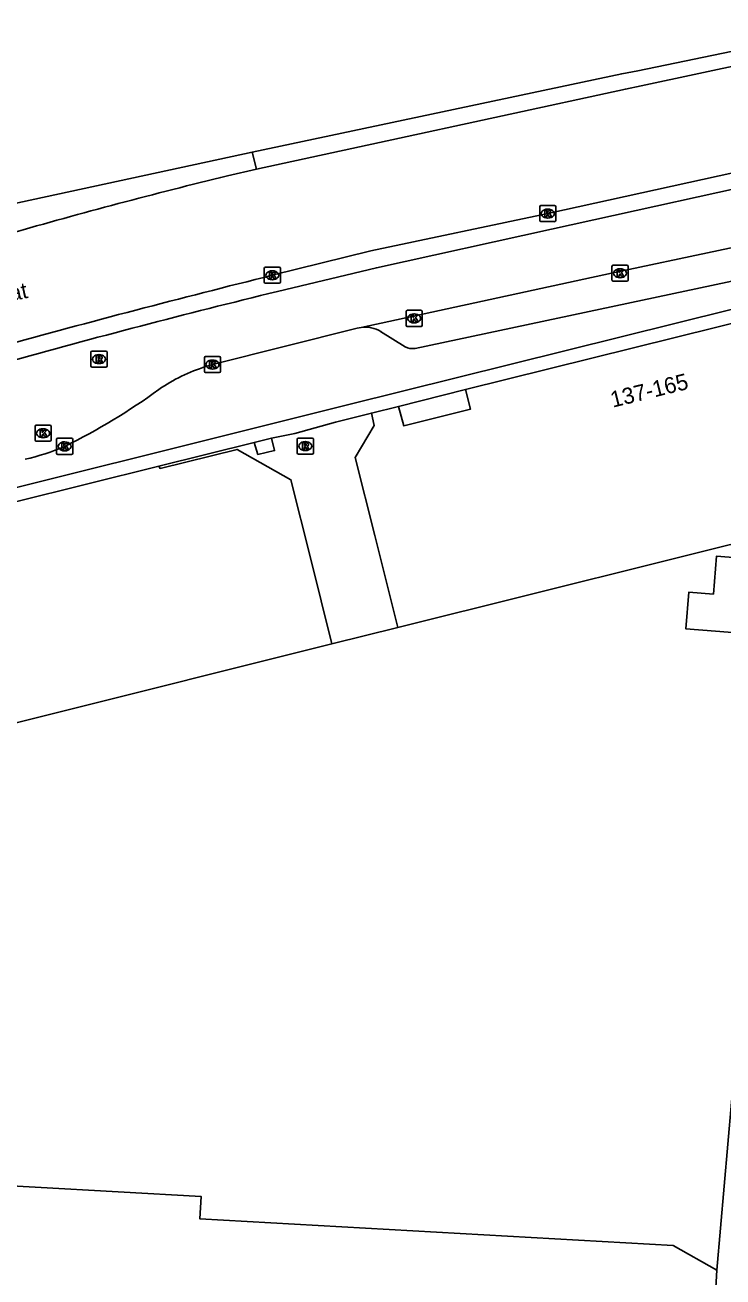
# Model space of a CAD drawing. Extents: x 160861 to 161308, y 384024 to 384878.
# Drawn here: x 160913.4 to 160956.7, y 384793.3 to 384871 of the extents above; entities that cross this region are included whole.
import ezdxf

# ---------------------------------------------------------------- set-up
doc = ezdxf.new("R2010")
doc.units = 0
for name, color, linetype in [('IMGEO_Berm_gesloten', 7, 'Continuous'), ('IMGEO_Erf', 7, 'Continuous'), ('IMGEO_Fietspad_gesloten', 7, 'Continuous'), ('IMGEO_Kolk', 7, 'Continuous'), ('IMGEO_Openbare_ruimte_label', 7, 'Continuous'), ('IMGEO_Pand', 7, 'Continuous'), ('IMGEO_Pand_nummerreeks', 7, 'Continuous'), ('IMGEO_Pand_overbouw', 7, 'Continuous'), ('IMGEO_Rijbaan_lokaal_open', 7, 'Continuous'), ('IMGEO_Rijbaan_regionaal_gesloten', 7, 'Continuous'), ('IMGEO_Rioolput', 7, 'Continuous'), ('IMGEO_Voetpad_open', 7, 'Continuous')]:
    doc.layers.add(name, color=color, linetype=linetype)

msp = doc.modelspace()

# ---------------------------------------------------------------- linework, layer by layer
at = {"layer": 'IMGEO_Berm_gesloten'}
msp.add_lwpolyline([(160927.748, 384862.071), (160927.48, 384863.128)], dxfattribs=at)
at = {"layer": 'IMGEO_Erf'}
msp.add_lwpolyline([(160958.824, 384833.185), (160959.001, 384835.447), (160966.05, 384834.898), (160966.234, 384837.263), (160956.254, 384838.041), (160956.072, 384835.701), (160954.55, 384835.82), (160954.371, 384833.532), (160958.824, 384833.185)], dxfattribs=at)
at = {"layer": 'IMGEO_Fietspad_gesloten'}
for points in [[(160965.533, 384862.563), (160961.596, 384861.765), (160946.03, 384858.331), (160935.179, 384855.945), (160929.044, 384854.477)], [(160934.227, 384852.244), (160949.744, 384855.609), (160963.013, 384858.428), (160966.201, 384859.13)], [(160924.6, 384849.813), (160925.012, 384849.941), (160933.981, 384852.191), (160934.227, 384852.244)]]:
    msp.add_lwpolyline(points, dxfattribs=at)
for centre, radius, start, end in [((161060.371, 384317.53), 552.774, 103.74361, 105.55791), ((160927.766, 384839.602), 10.69, 107.22679, 124.63629), ((160898.999, 384879.313), 38.349, 296.06689, 306.27811), ((160910.796, 384856.306), 12.508, 281.98394, 293.8334)]:
    msp.add_arc(centre, radius, start, end, dxfattribs=at)
at = {"layer": 'IMGEO_Kolk'}
for p, q in [((160945.3, 384858.88), (160945.3, 384859.732)), ((160945.375, 384859.806), (160946.227, 384859.806)), ((160946.301, 384859.732), (160946.301, 384858.88)), ((160945.811, 384859.026), (160945.786, 384859.026)), ((160945.788, 384859.586), (160945.813, 384859.586)), ((160946.227, 384858.806), (160945.375, 384858.806)), ((160928.223, 384855.054), (160928.223, 384855.906)), ((160928.298, 384855.98), (160929.15, 384855.98)), ((160929.224, 384855.906), (160929.224, 384855.054)), ((160949.782, 384855.179), (160949.782, 384856.031)), ((160949.857, 384856.105), (160950.709, 384856.105)), ((160950.27, 384855.885), (160950.295, 384855.885)), ((160950.783, 384856.031), (160950.783, 384855.179)), ((160928.734, 384855.2), (160928.709, 384855.2)), ((160928.711, 384855.76), (160928.736, 384855.76)), ((160950.709, 384855.105), (160949.857, 384855.105)), ((160950.293, 384855.325), (160950.268, 384855.325)), ((160929.15, 384854.98), (160928.298, 384854.98)), ((160937.017, 384852.379), (160937.017, 384853.231)), ((160937.092, 384853.305), (160937.944, 384853.305)), ((160937.505, 384853.085), (160937.53, 384853.085)), ((160938.018, 384853.231), (160938.018, 384852.379)), ((160937.944, 384852.305), (160937.092, 384852.305)), ((160937.528, 384852.525), (160937.503, 384852.525)), ((160924.511, 384849.515), (160924.511, 384850.367)), ((160924.586, 384850.441), (160925.438, 384850.441)), ((160925.512, 384850.367), (160925.512, 384849.515)), ((160925.022, 384849.661), (160924.997, 384849.661)), ((160924.999, 384850.221), (160925.024, 384850.221)), ((160925.438, 384849.441), (160924.586, 384849.441)), ((160914.012, 384845.253), (160914.012, 384846.105)), ((160914.087, 384846.179), (160914.939, 384846.179)), ((160914.5, 384845.959), (160914.525, 384845.959)), ((160915.013, 384846.105), (160915.013, 384845.253)), ((160914.939, 384845.179), (160914.087, 384845.179)), ((160914.523, 384845.399), (160914.498, 384845.399)), ((160915.349, 384844.439), (160915.349, 384845.291)), ((160915.424, 384845.365), (160916.276, 384845.365)), ((160915.837, 384845.145), (160915.862, 384845.145)), ((160916.35, 384845.291), (160916.35, 384844.439)), ((160916.276, 384844.365), (160915.424, 384844.365)), ((160915.86, 384844.585), (160915.835, 384844.585))]:
    msp.add_line(p, q, dxfattribs=at)
for points in [[(160945.3, 384858.88), (160945.3, 384859.732)], [(160945.375, 384859.806), (160946.227, 384859.806)], [(160946.301, 384859.732), (160946.301, 384858.88)], [(160945.621, 384859.506), (160945.744, 384859.506), (160945.744, 384859.355), (160945.874, 384859.506), (160946.038, 384859.506), (160945.892, 384859.355), (160946.045, 384859.106), (160945.893, 384859.106), (160945.808, 384859.27), (160945.744, 384859.203), (160945.744, 384859.106), (160945.621, 384859.106), (160945.621, 384859.506)], [(160946.227, 384858.806), (160945.375, 384858.806)], [(160928.223, 384855.054), (160928.223, 384855.906)], [(160928.298, 384855.98), (160929.15, 384855.98)], [(160929.224, 384855.906), (160929.224, 384855.054)], [(160949.782, 384855.179), (160949.782, 384856.031)], [(160949.857, 384856.105), (160950.709, 384856.105)], [(160950.103, 384855.805), (160950.226, 384855.805), (160950.226, 384855.654), (160950.356, 384855.805), (160950.52, 384855.805), (160950.374, 384855.654), (160950.527, 384855.405), (160950.375, 384855.405), (160950.29, 384855.569), (160950.226, 384855.502), (160950.226, 384855.405), (160950.103, 384855.405), (160950.103, 384855.805)], [(160950.783, 384856.031), (160950.783, 384855.179)], [(160928.544, 384855.68), (160928.667, 384855.68), (160928.667, 384855.529), (160928.797, 384855.68), (160928.961, 384855.68), (160928.815, 384855.529), (160928.968, 384855.28), (160928.816, 384855.28), (160928.731, 384855.444), (160928.667, 384855.377), (160928.667, 384855.28), (160928.544, 384855.28), (160928.544, 384855.68)], [(160950.709, 384855.105), (160949.857, 384855.105)], [(160929.15, 384854.98), (160928.298, 384854.98)], [(160937.017, 384852.379), (160937.017, 384853.231)], [(160937.092, 384853.305), (160937.944, 384853.305)], [(160937.338, 384853.005), (160937.461, 384853.005), (160937.461, 384852.854), (160937.591, 384853.005), (160937.755, 384853.005), (160937.609, 384852.854), (160937.762, 384852.605), (160937.61, 384852.605), (160937.525, 384852.769), (160937.461, 384852.702), (160937.461, 384852.605), (160937.338, 384852.605), (160937.338, 384853.005)], [(160938.018, 384853.231), (160938.018, 384852.379)], [(160937.944, 384852.305), (160937.092, 384852.305)], [(160924.511, 384849.515), (160924.511, 384850.367)], [(160924.586, 384850.441), (160925.438, 384850.441)], [(160925.512, 384850.367), (160925.512, 384849.515)], [(160924.832, 384850.141), (160924.955, 384850.141), (160924.955, 384849.99), (160925.085, 384850.141), (160925.249, 384850.141), (160925.103, 384849.99), (160925.256, 384849.741), (160925.104, 384849.741), (160925.019, 384849.905), (160924.955, 384849.838), (160924.955, 384849.741), (160924.832, 384849.741), (160924.832, 384850.141)], [(160925.438, 384849.441), (160924.586, 384849.441)], [(160914.012, 384845.253), (160914.012, 384846.105)], [(160914.087, 384846.179), (160914.939, 384846.179)], [(160914.333, 384845.879), (160914.456, 384845.879), (160914.456, 384845.728), (160914.586, 384845.879), (160914.75, 384845.879), (160914.604, 384845.728), (160914.757, 384845.479), (160914.605, 384845.479), (160914.52, 384845.643), (160914.456, 384845.576), (160914.456, 384845.479), (160914.333, 384845.479), (160914.333, 384845.879)], [(160915.013, 384846.105), (160915.013, 384845.253)], [(160914.939, 384845.179), (160914.087, 384845.179)], [(160915.349, 384844.439), (160915.349, 384845.291)], [(160915.424, 384845.365), (160916.276, 384845.365)], [(160915.67, 384845.065), (160915.793, 384845.065), (160915.793, 384844.914), (160915.923, 384845.065), (160916.087, 384845.065), (160915.941, 384844.914), (160916.094, 384844.665), (160915.942, 384844.665), (160915.857, 384844.829), (160915.793, 384844.762), (160915.793, 384844.665), (160915.67, 384844.665), (160915.67, 384845.065)], [(160916.35, 384845.291), (160916.35, 384844.439)], [(160916.276, 384844.365), (160915.424, 384844.365)]]:
    msp.add_lwpolyline(points, dxfattribs=at)
for centre, start, end in [((160945.377, 384859.73), 91.55205, 178.44795), ((160945.377, 384859.73), 91.55205, 178.44795), ((160946.225, 384859.73), 1.55205, 88.44795), ((160946.225, 384859.73), 1.55205, 88.44795), ((160945.377, 384858.882), 181.55205, 268.44795), ((160945.377, 384858.882), 181.55205, 268.44795), ((160946.225, 384858.882), 271.55205, 358.44795), ((160946.225, 384858.882), 271.55205, 358.44795), ((160928.3, 384855.904), 91.55205, 178.44795), ((160928.3, 384855.904), 91.55205, 178.44795), ((160929.148, 384855.904), 1.55205, 88.44795), ((160929.148, 384855.904), 1.55205, 88.44795), ((160949.859, 384856.029), 91.55205, 178.44795), ((160949.859, 384856.029), 91.55205, 178.44795), ((160950.707, 384856.029), 1.55205, 88.44795), ((160950.707, 384856.029), 1.55205, 88.44795), ((160928.3, 384855.056), 181.55205, 268.44795), ((160928.3, 384855.056), 181.55205, 268.44795), ((160929.148, 384855.056), 271.55205, 358.44795), ((160929.148, 384855.056), 271.55205, 358.44795), ((160949.859, 384855.181), 181.55205, 268.44795), ((160949.859, 384855.181), 181.55205, 268.44795), ((160950.707, 384855.181), 271.55205, 358.44795), ((160950.707, 384855.181), 271.55205, 358.44795), ((160937.094, 384853.229), 91.55205, 178.44795), ((160937.094, 384853.229), 91.55205, 178.44795), ((160937.942, 384853.229), 1.55205, 88.44795), ((160937.942, 384853.229), 1.55205, 88.44795), ((160937.094, 384852.381), 181.55205, 268.44795), ((160937.094, 384852.381), 181.55205, 268.44795), ((160937.942, 384852.381), 271.55205, 358.44795), ((160937.942, 384852.381), 271.55205, 358.44795), ((160924.588, 384850.365), 91.55205, 178.44795), ((160924.588, 384850.365), 91.55205, 178.44795), ((160925.436, 384850.365), 1.55205, 88.44795), ((160925.436, 384850.365), 1.55205, 88.44795), ((160924.588, 384849.517), 181.55205, 268.44795), ((160924.588, 384849.517), 181.55205, 268.44795), ((160925.436, 384849.517), 271.55205, 358.44795), ((160925.436, 384849.517), 271.55205, 358.44795), ((160914.089, 384846.103), 91.55205, 178.44795), ((160914.089, 384846.103), 91.55205, 178.44795), ((160914.937, 384846.103), 1.55205, 88.44795), ((160914.937, 384846.103), 1.55205, 88.44795), ((160914.089, 384845.255), 181.55205, 268.44795), ((160914.089, 384845.255), 181.55205, 268.44795), ((160914.937, 384845.255), 271.55205, 358.44795), ((160914.937, 384845.255), 271.55205, 358.44795), ((160915.426, 384845.289), 91.55205, 178.44795), ((160915.426, 384845.289), 91.55205, 178.44795), ((160916.274, 384845.289), 1.55205, 88.44795), ((160916.274, 384845.289), 1.55205, 88.44795), ((160915.426, 384844.441), 181.55205, 268.44795), ((160915.426, 384844.441), 181.55205, 268.44795), ((160916.274, 384844.441), 271.55205, 358.44795), ((160916.274, 384844.441), 271.55205, 358.44795)]:
    msp.add_arc(centre, 0.0765, start, end, dxfattribs=at)
for centre, major_axis, ratio, start_param, end_param in [((160945.787, 384859.306), (-0.387, 0.002), 0.722429, 4.712389, 7.853982), ((160945.812, 384859.306), (-0.39, 0.002), 0.717154, 1.570796, 4.712389), ((160950.269, 384855.605), (-0.387, 0.002), 0.722429, 4.712389, 7.853982), ((160950.294, 384855.605), (-0.39, 0.002), 0.717154, 1.570796, 4.712389), ((160928.71, 384855.48), (-0.387, 0.002), 0.722429, 4.712389, 7.853982), ((160928.735, 384855.48), (-0.39, 0.002), 0.717154, 1.570796, 4.712389), ((160937.504, 384852.805), (-0.387, 0.002), 0.722429, 4.712389, 7.853982), ((160937.529, 384852.805), (-0.39, 0.002), 0.717154, 1.570796, 4.712389), ((160924.998, 384849.941), (-0.387, 0.002), 0.722429, 4.712389, 7.853982), ((160925.023, 384849.941), (-0.39, 0.002), 0.717154, 1.570796, 4.712389), ((160914.499, 384845.679), (-0.387, 0.002), 0.722429, 4.712389, 7.853982), ((160914.524, 384845.679), (-0.39, 0.002), 0.717154, 1.570796, 4.712389), ((160915.836, 384844.865), (-0.387, 0.002), 0.722429, 4.712389, 7.853982), ((160915.861, 384844.865), (-0.39, 0.002), 0.717154, 1.570796, 4.712389)]:
    msp.add_ellipse(centre, major_axis=major_axis, ratio=ratio, start_param=start_param, end_param=end_param, dxfattribs=at)
at = {"layer": 'IMGEO_Pand'}
for points in [[(160964.114, 384854.203), (160940.701, 384848.385)], [(160940.701, 384848.385), (160941.007, 384847.17), (160936.87, 384846.14), (160936.557, 384847.335)], [(160936.557, 384847.335), (160934.872, 384846.924)], [(160934.872, 384846.924), (160935.042, 384846.159), (160933.864, 384844.174), (160935.077, 384839.324), (160936.502, 384833.624)], [(160927.59, 384845.102), (160927.827, 384844.364), (160928.861, 384844.6), (160928.672, 384845.37)], [(160928.672, 384845.37), (160927.59, 384845.102)], [(160932.413, 384832.61), (160931.083, 384837.943), (160929.872, 384842.794), (160926.541, 384844.679), (160921.769, 384843.497), (160921.689, 384843.63)], [(160921.689, 384843.63), (160912.72, 384841.407)], [(160936.502, 384833.624), (160961.197, 384839.783), (160966.048, 384840.993), (160966.03, 384841.11)], [(160887.275, 384809.297), (160888.199, 384809.678), (160896.629, 384823.652), (160932.413, 384832.61)], [(160956.275, 384793.744), (160953.576, 384795.276), (160924.223, 384796.935), (160924.302, 384798.324), (160908.857, 384799.197)], [(160956.275, 384793.744), (160955.868, 384786.532)]]:
    msp.add_lwpolyline(points, dxfattribs=at)
at = {"layer": 'IMGEO_Pand_overbouw'}
msp.add_lwpolyline([(160928.672, 384845.37), (160928.861, 384844.6), (160927.827, 384844.364), (160927.59, 384845.102), (160921.689, 384843.63), (160921.769, 384843.497), (160926.541, 384844.679), (160929.872, 384842.794), (160931.083, 384837.943), (160932.413, 384832.61), (160936.502, 384833.624), (160935.077, 384839.324), (160933.864, 384844.174), (160935.042, 384846.159), (160934.872, 384846.924), (160932.636, 384846.362), (160930.127, 384845.653)], close=True, dxfattribs=at)
at = {"layer": 'IMGEO_Rijbaan_lokaal_open'}
for points in [[(160934.872, 384846.924), (160932.636, 384846.362), (160930.127, 384845.653), (160928.672, 384845.37)], [(160927.59, 384845.102), (160921.689, 384843.63)], [(160932.413, 384832.61), (160936.502, 384833.624)]]:
    msp.add_lwpolyline(points, dxfattribs=at)
at = {"layer": 'IMGEO_Rijbaan_regionaal_gesloten'}
for points in [[(160927.48, 384863.128), (160950.387, 384867.981), (160951.392, 384868.17), (160958.365, 384869.618), (160965.245, 384871.006)], [(160965.312, 384870.179), (160951.596, 384867.24), (160950.617, 384867.03), (160927.748, 384862.071)], [(160928.724, 384855.48), (160934.839, 384856.988), (160945.801, 384859.306), (160966.015, 384863.765)], [(160876.331, 384852.047), (160927.48, 384863.128)], [(160927.748, 384862.071), (160925.954, 384861.652)]]:
    msp.add_lwpolyline(points, dxfattribs=at)
for centre, radius, start, end in [((161004.737, 384537.85), 333.248, 103.67478, 106.08153), ((161111.9, 384121.418), 756.572, 104.011306, 105.335745)]:
    msp.add_arc(centre, radius, start, end, dxfattribs=at)
at = {"layer": 'IMGEO_Rioolput'}
for p, q in [((160917.474, 384849.851), (160917.474, 384850.703)), ((160917.549, 384850.777), (160918.401, 384850.777)), ((160917.962, 384850.557), (160917.987, 384850.557)), ((160918.475, 384850.703), (160918.475, 384849.851)), ((160918.401, 384849.777), (160917.549, 384849.777)), ((160917.985, 384849.997), (160917.96, 384849.997)), ((160930.267, 384844.456), (160930.267, 384845.308)), ((160930.342, 384845.382), (160931.194, 384845.382)), ((160930.755, 384845.162), (160930.78, 384845.162)), ((160931.268, 384845.308), (160931.268, 384844.456)), ((160931.194, 384844.382), (160930.342, 384844.382)), ((160930.778, 384844.602), (160930.753, 384844.602))]:
    msp.add_line(p, q, dxfattribs=at)
for points in [[(160917.474, 384849.851), (160917.474, 384850.703)], [(160917.549, 384850.777), (160918.401, 384850.777)], [(160918.063, 384850.475), (160917.811, 384850.477), (160917.811, 384850.077)], [(160917.989, 384850.396), (160917.935, 384850.396), (160917.935, 384850.315)], [(160918.475, 384850.703), (160918.475, 384849.851)], [(160918.401, 384849.777), (160917.549, 384849.777)], [(160917.811, 384850.077), (160917.935, 384850.077), (160917.935, 384850.239), (160917.946, 384850.239)], [(160917.935, 384850.315), (160917.987, 384850.315)], [(160917.993, 384850.21), (160918.064, 384850.077), (160918.204, 384850.077), (160918.139, 384850.203)], [(160930.267, 384844.456), (160930.267, 384845.308)], [(160930.342, 384845.382), (160931.194, 384845.382)], [(160930.856, 384845.08), (160930.604, 384845.082), (160930.604, 384844.682)], [(160930.782, 384845.001), (160930.728, 384845.001), (160930.728, 384844.92)], [(160931.268, 384845.308), (160931.268, 384844.456)], [(160931.194, 384844.382), (160930.342, 384844.382)], [(160930.604, 384844.682), (160930.728, 384844.682), (160930.728, 384844.844), (160930.739, 384844.844)], [(160930.728, 384844.92), (160930.78, 384844.92)], [(160930.786, 384844.815), (160930.857, 384844.682), (160930.997, 384844.682), (160930.932, 384844.808)]]:
    msp.add_lwpolyline(points, dxfattribs=at)
for centre, radius, start, end in [((160917.551, 384850.701), 0.0765, 91.55205, 178.44795), ((160917.551, 384850.701), 0.0765, 91.55205, 178.44795), ((160917.995, 384850.3), 0.0964, 77.00612, 93.18647), ((160918.009, 384850.357), 0.0378, 276.66336, 79.67722), ((160918.062, 384850.365), 0.109, 350.36119, 89.41601), ((160918.399, 384850.701), 0.0765, 1.55205, 88.44795), ((160918.399, 384850.701), 0.0765, 1.55205, 88.44795), ((160917.551, 384849.853), 0.0765, 181.55205, 268.44795), ((160917.551, 384849.853), 0.0765, 181.55205, 268.44795), ((160917.945, 384850.186), 0.0533, 26.02933, 88.69889), ((160917.971, 384850.504), 0.19, 274.7715, 282.96867), ((160918.06, 384850.365), 0.112, 277.58423, 350.98172), ((160918.044, 384850.15), 0.108, 29.51342, 73.79051), ((160918.399, 384849.853), 0.0765, 271.55205, 358.44795), ((160918.399, 384849.853), 0.0765, 271.55205, 358.44795), ((160930.344, 384845.306), 0.0765, 91.55205, 178.44795), ((160930.344, 384845.306), 0.0765, 91.55205, 178.44795), ((160930.764, 384845.109), 0.19, 274.7715, 282.96867), ((160930.788, 384844.905), 0.0964, 77.00612, 93.18647), ((160930.802, 384844.962), 0.0378, 276.66336, 79.67722), ((160930.855, 384844.97), 0.109, 350.36119, 89.41601), ((160930.853, 384844.97), 0.112, 277.58423, 350.98172), ((160931.192, 384845.306), 0.0765, 1.55205, 88.44795), ((160931.192, 384845.306), 0.0765, 1.55205, 88.44795), ((160930.344, 384844.458), 0.0765, 181.55205, 268.44795), ((160930.344, 384844.458), 0.0765, 181.55205, 268.44795), ((160930.738, 384844.791), 0.0533, 26.02933, 88.69889), ((160930.837, 384844.755), 0.108, 29.51342, 73.79051), ((160931.192, 384844.458), 0.0765, 271.55205, 358.44795), ((160931.192, 384844.458), 0.0765, 271.55205, 358.44795)]:
    msp.add_arc(centre, radius, start, end, dxfattribs=at)
for centre, major_axis, ratio, start_param, end_param in [((160917.961, 384850.277), (-0.387, 0.002), 0.722429, 4.712389, 7.853982), ((160917.986, 384850.277), (-0.39, 0.002), 0.717154, 1.570796, 4.712389), ((160930.754, 384844.882), (-0.387, 0.002), 0.722429, 4.712389, 7.853982), ((160930.779, 384844.882), (-0.39, 0.002), 0.717154, 1.570796, 4.712389)]:
    msp.add_ellipse(centre, major_axis=major_axis, ratio=ratio, start_param=start_param, end_param=end_param, dxfattribs=at)
at = {"layer": 'IMGEO_Voetpad_open'}
for points in [[(160964.035, 384856.587), (160963.14, 384856.385), (160937.579, 384850.927)], [(160889.382, 384835.598), (160889.152, 384835.522), (160888.676, 384836.263), (160928.998, 384846.338), (160933.394, 384847.435), (160963.917, 384855.031), (160964.114, 384854.203)], [(160936.952, 384851.034), (160935.441, 384851.991)], [(160936.557, 384847.335), (160940.701, 384848.385)], [(160959.326, 384823.509), (160958.656, 384823.569), (160958.566, 384819.819), (160956.275, 384793.744)]]:
    msp.add_lwpolyline(points, dxfattribs=at)
for centre, radius, start, end in [((160934.488, 384850.457), 1.806, 58.14675, 98.30914), ((160937.496, 384852.333), 1.409, 247.26815, 273.36294)]:
    msp.add_arc(centre, radius, start, end, dxfattribs=at)

# ---------------------------------------------------------------- texts
at = {"layer": 'IMGEO_Openbare_ruimte_label'}
msp.add_text('Pastoriestraat', height=1, rotation=12.18684, dxfattribs=at).set_placement((160905.556, 384852.343))
at = {"layer": 'IMGEO_Pand_nummerreeks'}
msp.add_text('137-165', height=1, rotation=13.95725, dxfattribs=at).set_placement((160949.828, 384847.259))

doc.saveas('drawing.dxf')
